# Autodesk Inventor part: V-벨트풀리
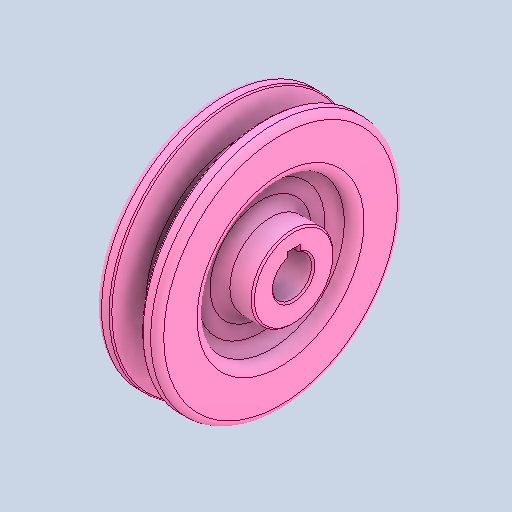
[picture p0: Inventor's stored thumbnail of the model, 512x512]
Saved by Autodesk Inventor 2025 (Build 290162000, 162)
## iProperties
Created: 2024-07
Part Number: V-벨트풀리
Material: 강철, 탄소
Document SubType Name: Modeling
Designer: 학생
Density: 7.87 g/cm^3
Appearance: 기본값
Author: jhkim
Sending System: Autodesk Inventor 2025
Preprocessor: ST-DEVELOPER v20
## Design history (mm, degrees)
feature "솔리드1"
node "솔리드2"
